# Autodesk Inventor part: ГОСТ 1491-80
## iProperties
Created: 2009-12
Part Number: ГОСТ 1491-80
Document SubType Name: Modeling
Designer: Роман
Density: 1 g/cm^3
Mass: 0.431296 g
Surface Area: 5.09914 cm^2
Volume: 0.431296 cm^3
Author: Роман
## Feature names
1. Revolution1
2. Chamfer1
3. Extrusion1
